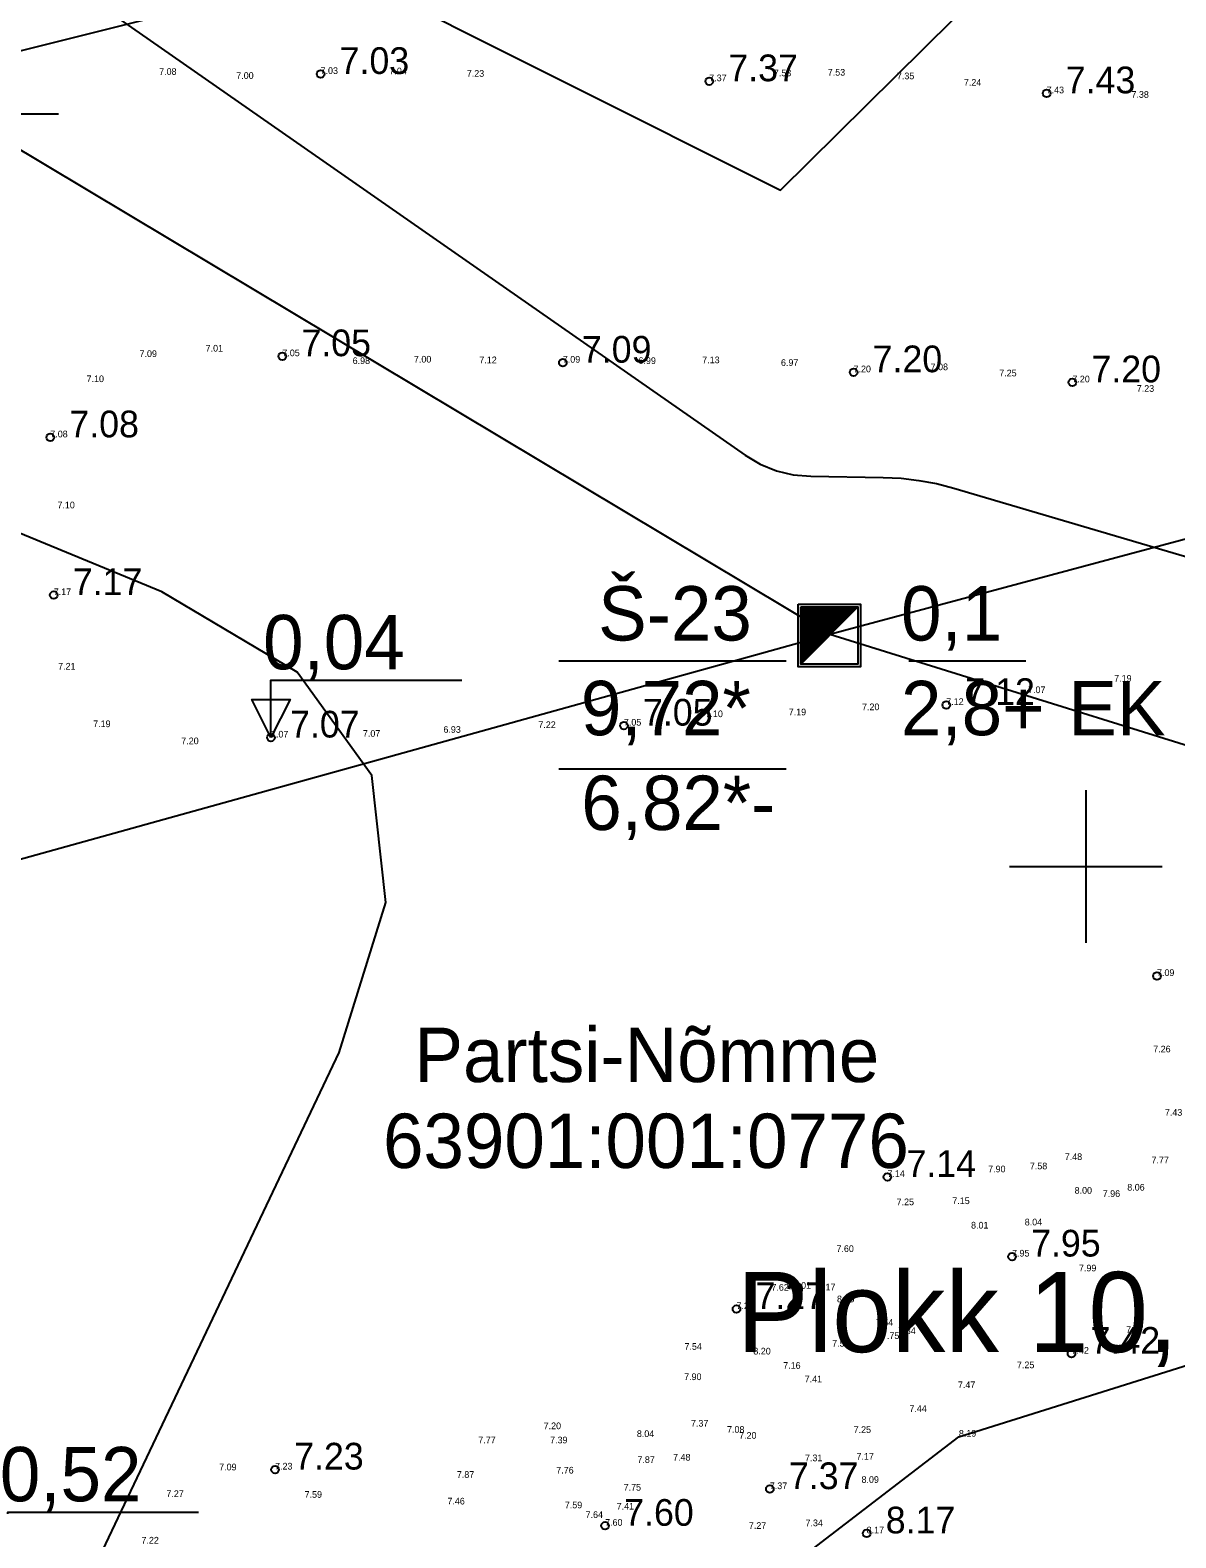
# Model space of a CAD drawing. Extents: x 433497 to 434382, y 6534486 to 6534993.
# Drawn here: x 433944.7 to 434004.7, y 6534764.8 to 6534843.8 of the extents above; entities that cross this region are included whole.
import ezdxf

# ---------------------------------------------------------------- set-up
doc = ezdxf.new("R2010")
doc.units = 0
for name, color, linetype in [('GEOLPUNKT', 7, 'Continuous'), ('jääkpaksus', 7, 'Continuous'), ('kataster', 7, 'Continuous'), ('KORGUS-EH2000', 7, 'Continuous'), ('l__x00e4__bil__x00f5__iked', 7, 'Continuous'), ('Lamami horisontaal', 7, 'Continuous'), ('MOOTKORG-EH2000', 7, 'Continuous'), ('PIIR', 7, 'Continuous'), ('VEEKOGU', 7, 'Continuous'), ('VORK', 7, 'Continuous')]:
    doc.layers.add(name, color=color, linetype=linetype)

msp = doc.modelspace()

# ---------------------------------------------------------------- linework, layer by layer
at = {"layer": 'GEOLPUNKT'}
for p, q in [((433985.055, 6534810.608), (433988.055, 6534813.608)), ((433985.055, 6534810.638), (433988.024, 6534813.608)), ((433985.055, 6534810.709), (433987.953, 6534813.608)), ((433985.055, 6534810.78), (433987.883, 6534813.608)), ((433985.055, 6534810.85), (433987.812, 6534813.608)), ((433985.055, 6534810.921), (433987.741, 6534813.608)), ((433985.055, 6534810.992), (433987.671, 6534813.608)), ((433985.055, 6534811.062), (433987.6, 6534813.608)), ((433985.055, 6534811.133), (433987.529, 6534813.608)), ((433985.055, 6534811.204), (433987.458, 6534813.608)), ((433985.055, 6534811.275), (433987.388, 6534813.608)), ((433985.055, 6534811.345), (433987.317, 6534813.608)), ((433985.055, 6534811.416), (433987.246, 6534813.608)), ((433985.055, 6534811.487), (433987.176, 6534813.608)), ((433985.055, 6534811.557), (433987.105, 6534813.608)), ((433985.055, 6534811.628), (433987.034, 6534813.608)), ((433985.055, 6534811.699), (433986.963, 6534813.608)), ((433985.055, 6534811.77), (433986.893, 6534813.608)), ((433985.055, 6534811.84), (433986.822, 6534813.608)), ((433985.055, 6534811.911), (433986.751, 6534813.608)), ((433985.055, 6534811.982), (433986.681, 6534813.608)), ((433985.055, 6534812.052), (433986.61, 6534813.608)), ((433985.055, 6534812.123), (433986.539, 6534813.608)), ((433985.055, 6534812.194), (433986.468, 6534813.608)), ((433985.055, 6534812.265), (433986.398, 6534813.608)), ((433985.055, 6534812.335), (433986.327, 6534813.608)), ((433985.055, 6534812.406), (433986.256, 6534813.608)), ((433985.055, 6534812.477), (433986.186, 6534813.608)), ((433985.055, 6534812.547), (433986.115, 6534813.608)), ((433985.055, 6534812.618), (433986.044, 6534813.608)), ((433985.055, 6534812.689), (433985.973, 6534813.608)), ((433985.055, 6534812.759), (433985.903, 6534813.608)), ((433985.055, 6534812.83), (433985.832, 6534813.608)), ((433985.055, 6534812.901), (433985.761, 6534813.608)), ((433985.055, 6534812.972), (433985.691, 6534813.608)), ((433985.055, 6534813.042), (433985.62, 6534813.608)), ((433985.055, 6534813.113), (433985.549, 6534813.608)), ((433985.055, 6534813.184), (433985.478, 6534813.608)), ((433985.055, 6534813.254), (433985.408, 6534813.608)), ((433985.055, 6534813.325), (433985.337, 6534813.608)), ((433985.055, 6534813.396), (433985.266, 6534813.608)), ((433985.055, 6534813.467), (433985.196, 6534813.608)), ((433985.055, 6534813.537), (433985.125, 6534813.608)), ((433986.555, 6534812.108), (433986.555, 6534812.108))]:
    msp.add_line(p, q, dxfattribs=at)
for points in [[(433984.914, 6534813.749), (433988.196, 6534813.749), (433988.196, 6534810.467), (433984.914, 6534810.467)], [(433985.055, 6534813.608), (433988.055, 6534813.608), (433988.055, 6534810.608), (433985.055, 6534810.608)]]:
    msp.add_lwpolyline(points, close=True, dxfattribs=at)
for points in [[(433972.379, 6534810.783), (433984.296, 6534810.783)], [(433990.718, 6534810.783), (433996.846, 6534810.783)], [(433972.379, 6534805.129), (433984.296, 6534805.129)]]:
    msp.add_lwpolyline(points, dxfattribs=at)
at = {"layer": 'jääkpaksus'}
for points in [[(433936.167, 6534836.451), (433936.167, 6534839.451), (433946.167, 6534839.451)], [(433957.299, 6534806.762), (433957.299, 6534809.762), (433967.299, 6534809.762)], [(433943.508, 6534763.157), (433943.508, 6534766.157), (433953.508, 6534766.157)]]:
    msp.add_lwpolyline(points, dxfattribs=at)
msp.add_lwpolyline([(433957.299, 6534806.762), (433956.299, 6534808.762), (433958.299, 6534808.762)], close=True, dxfattribs=at)
at = {"layer": 'KORGUS-EH2000'}
for centre in [(433959.898, 6534841.538), (433980.263, 6534841.158), (433997.941, 6534840.525), (433957.896, 6534826.746), (433972.591, 6534826.408), (433987.824, 6534825.906), (433999.289, 6534825.376), (433945.737, 6534822.494), (433945.916, 6534814.224), (433992.68, 6534808.467), (433975.791, 6534807.386), (433957.299, 6534806.762), (434003.722, 6534794.265), (433989.601, 6534783.734), (433996.128, 6534779.561), (433981.69, 6534776.808), (433999.243, 6534774.468), (433957.514, 6534768.398), (433983.437, 6534767.371), (433974.806, 6534765.45), (433988.511, 6534765.051)]:
    msp.add_circle(centre, 0.2, dxfattribs=at)
at = {"layer": 'l__x00e4__bil__x00f5__iked'}
for points in [[(433837.129, 6534901.88), (433863.279, 6534885.992), (433986.579, 6534812.177), (434090.185, 6534779.904), (434120.969, 6534768.153)], [(433620.07, 6534691.039), (433627.105, 6534692.187), (433736.834, 6534712.709), (433742.792, 6534710.723), (433822.234, 6534766.498), (433986.579, 6534812.177), (434120.472, 6534848.091), (434132.163, 6534850.175)]]:
    msp.add_lwpolyline(points, dxfattribs=at)
at = {"layer": 'Lamami horisontaal'}
for points in [[(433873.126, 6534888.995), (433873.76, 6534889.15), (433880.129, 6534889.137), (433886.285, 6534887.502), (433892.228, 6534884.245), (433982.141, 6534821.565), (433982.939, 6534821.09), (433983.78, 6534820.746), (433984.663, 6534820.534), (433985.588, 6534820.453), (433989.375, 6534820.395), (433990.317, 6534820.349), (433991.249, 6534820.24), (433992.172, 6534820.067), (433993.085, 6534819.831), (434065.946, 6534798.347)], [(433937.053, 6534740.112), (433960.879, 6534790.248), (433963.322, 6534798.12), (433962.586, 6534804.768), (433958.672, 6534810.191), (433951.578, 6534814.39), (433862.504, 6534851.176), (433857.642, 6534852.614), (433852.859, 6534852.881), (433848.155, 6534851.977), (433843.529, 6534849.902), (433823.019, 6534838.004), (433819.889, 6534836.728), (433817.507, 6534836.964), (433815.874, 6534838.714), (433814.99, 6534841.977), (433812.452, 6534861.972), (433812.459, 6534863.884), (433813.004, 6534865.497), (433813.579, 6534866.195)]]:
    msp.add_lwpolyline(points, dxfattribs=at)
at = {"layer": 'PIIR'}
msp.add_lwpolyline([(433924.608, 6534718.343), (433917.99, 6534737.895), (433917.54, 6534763.005), (433913.58, 6534784.995), (433921.17, 6534796.005), (433926.99, 6534825.75), (433941, 6534841.965), (433961.01, 6534846.975), (433983.99, 6534835.44), (434035.235, 6534886.132)], dxfattribs=at)
at = {"layer": 'VEEKOGU'}
msp.add_lwpolyline([(433990.248, 6534745.091), (433989.229, 6534747.928), (433987.385, 6534749.949), (433991.313, 6534753.223), (433990.848, 6534757.342), (433983.632, 6534758.762), (433984.921, 6534763.647), (433993.342, 6534770.119), (434007.795, 6534774.659), (434015.787, 6534777.524), (434021.334, 6534780.065), (434019.838, 6534775.271), (434024.742, 6534771.609), (434032.769, 6534771.363), (434040.593, 6534769.95), (434030.645, 6534764.016), (434026.863, 6534763.673), (434020.295, 6534765.501), (434016.352, 6534765.657), (434007.919, 6534762.574), (434004.918, 6534761.482), (434000.685, 6534758.332), (433996.369, 6534756.857), (433990.248, 6534745.091)], dxfattribs=at)
msp.add_lwpolyline([(433990.248, 6534745.091), (433989.229, 6534747.928), (433987.385, 6534749.949), (433991.313, 6534753.223), (433990.848, 6534757.342), (433983.632, 6534758.762), (433984.921, 6534763.647), (433993.342, 6534770.119), (434007.795, 6534774.659), (434015.787, 6534777.524), (434021.334, 6534780.065), (434019.838, 6534775.271), (434024.742, 6534771.609), (434032.769, 6534771.363), (434040.593, 6534769.95), (434030.645, 6534764.016), (434026.863, 6534763.673), (434020.295, 6534765.501), (434016.352, 6534765.657), (434007.919, 6534762.574), (434004.918, 6534761.482), (434000.685, 6534758.332), (433996.369, 6534756.857), (433990.248, 6534745.091)], dxfattribs=at)
at = {"layer": 'VORK'}
for p, q in [((434000, 6534804), (434000, 6534796)), ((433996, 6534800), (434004, 6534800))]:
    msp.add_line(p, q, dxfattribs=at)

# ---------------------------------------------------------------- texts
at = {"layer": 'GEOLPUNKT'}
for s, p in [('Š-23', (433974.442, 6534811.846)), ('0,1', (433990.31, 6534811.846)), ('9,72*', (433973.539, 6534806.881)), ('9,72*', (433973.539, 6534806.881)), ('2,8+', (433990.31, 6534806.881)), ('EK', (433999.082, 6534806.881)), ('6,82*-', (433973.558, 6534801.916))]:
    msp.add_text(s, height=2.85, dxfattribs=at).set_placement(p)
at = {"layer": 'jääkpaksus'}
for s, p in [('0,04', (433956.887, 6534810.337)), ('0,52', (433943.096, 6534766.732))]:
    msp.add_text(s, height=2.85, rotation=360, dxfattribs=at).set_placement(p)
at = {"layer": 'kataster'}
for s, p in [('Partsi-Nõmme', (433964.819, 6534788.705)), ('63901:001:0776', (433963.17, 6534784.202))]:
    msp.add_text(s, height=2.85, dxfattribs=at).set_placement(p)
at = {"layer": 'KORGUS-EH2000'}
for s, p in [('7.03', (433960.898, 6534841.538)), ('7.37', (433981.263, 6534841.158)), ('7.43', (433998.941, 6534840.525)), ('7.05', (433958.896, 6534826.746)), ('7.09', (433973.591, 6534826.408)), ('7.20', (433988.824, 6534825.906)), ('7.20', (434000.289, 6534825.376)), ('7.08', (433946.737, 6534822.494)), ('7.17', (433946.916, 6534814.224)), ('7.12', (433993.68, 6534808.467)), ('7.07', (433958.299, 6534806.762)), ('7.05', (433976.791, 6534807.386)), ('7.14', (433990.601, 6534783.734)), ('7.95', (433997.128, 6534779.561)), ('7.27', (433982.69, 6534776.808)), ('7.42', (434000.243, 6534774.468)), ('7.23', (433958.514, 6534768.398)), ('7.37', (433984.437, 6534767.371)), ('7.60', (433975.806, 6534765.45)), ('8.17', (433989.511, 6534765.051))]:
    msp.add_text(s, height=1.4, dxfattribs=at).set_placement(p)
at = {"layer": 'MOOTKORG-EH2000'}
for s, p in [('7.08', (433951.441, 6534841.489)), ('7.00', (433955.481, 6534841.279)), ('7.03', (433959.898, 6534841.538)), ('7.04', (433963.503, 6534841.52)), ('7.23', (433967.56, 6534841.392)), ('7.37', (433980.263, 6534841.158)), ('7.53', (433983.649, 6534841.42)), ('7.53', (433986.473, 6534841.453)), ('7.35', (433990.095, 6534841.261)), ('7.24', (433993.605, 6534840.921)), ('7.43', (433997.941, 6534840.525)), ('7.38', (434002.385, 6534840.288)), ('7.09', (433950.413, 6534826.705)), ('7.01', (433953.876, 6534826.99)), ('7.05', (433957.896, 6534826.746)), ('6.98', (433961.58, 6534826.335)), ('7.00', (433964.79, 6534826.414)), ('7.12', (433968.218, 6534826.378)), ('7.09', (433972.591, 6534826.408)), ('6.99', (433976.556, 6534826.34)), ('7.13', (433979.895, 6534826.379)), ('6.97', (433984.02, 6534826.239)), ('7.20', (433987.824, 6534825.906)), ('7.08', (433991.862, 6534826.014)), ('7.10', (433947.639, 6534825.388)), ('7.25', (433995.457, 6534825.689)), ('7.20', (433999.289, 6534825.376)), ('7.23', (434002.662, 6534824.88)), ('7.08', (433945.737, 6534822.494)), ('7.10', (433946.112, 6534818.773)), ('7.17', (433945.916, 6534814.224)), ('7.21', (433946.148, 6534810.323)), ('7.19', (434001.478, 6534809.691)), ('7.07', (433996.967, 6534809.088)), ('7.10', (433980.067, 6534807.83)), ('7.19', (433984.427, 6534807.926)), ('7.20', (433988.267, 6534808.194)), ('7.12', (433992.68, 6534808.467)), ('7.19', (433947.984, 6534807.306)), ('6.93', (433966.334, 6534807.009)), ('7.22', (433971.31, 6534807.26)), ('7.05', (433975.791, 6534807.386)), ('7.20', (433952.6, 6534806.411)), ('7.07', (433957.299, 6534806.762)), ('7.07', (433962.116, 6534806.8)), ('7.09', (434003.722, 6534794.265)), ('7.26', (434003.525, 6534790.26)), ('7.43', (434004.137, 6534786.94)), ('7.58', (433997.061, 6534784.131)), ('7.48', (433998.89, 6534784.619)), ('7.77', (434003.434, 6534784.441)), ('7.14', (433989.601, 6534783.734)), ('7.90', (433994.876, 6534783.978)), ('8.00', (433999.406, 6534782.854)), ('7.96', (434000.879, 6534782.685)), ('8.06', (434002.165, 6534783.017)), ('7.25', (433990.081, 6534782.251)), ('7.15', (433992.998, 6534782.31)), ('8.01', (433993.98, 6534781.028)), ('8.04', (433996.794, 6534781.192)), ('7.60', (433986.929, 6534779.799)), ('7.95', (433996.128, 6534779.561)), ('7.99', (433999.634, 6534778.782)), ('7.62', (433983.52, 6534777.773)), ('8.01', (433984.685, 6534777.871)), ('8.17', (433985.965, 6534777.786)), ('8.15', (433986.954, 6534777.164)), ('7.27', (433981.69, 6534776.808)), ('7.54', (433988.991, 6534775.935)), ('7.84', (433990.17, 6534775.496)), ('7.57', (434002.102, 6534775.55)), ('7.54', (433978.965, 6534774.673)), ('7.51', (433986.703, 6534774.839)), ('7.75', (433989.312, 6534775.243)), ('8.20', (433982.573, 6534774.428)), ('7.42', (433999.243, 6534774.468)), ('7.90', (433978.947, 6534773.085)), ('7.16', (433984.138, 6534773.676)), ('7.25', (433996.385, 6534773.708)), ('7.41', (433985.263, 6534772.967)), ('7.47', (433993.292, 6534772.663)), ('7.44', (433990.75, 6534771.42)), ('7.37', (433979.306, 6534770.648)), ('7.20', (433971.587, 6534770.513)), ('8.04', (433976.47, 6534770.102)), ('7.08', (433981.195, 6534770.322)), ('7.20', (433981.826, 6534770.008)), ('7.25', (433987.83, 6534770.316)), ('8.19', (433993.342, 6534770.119)), ('7.77', (433968.163, 6534769.772)), ('7.39', (433971.924, 6534769.771)), ('7.09', (433954.585, 6534768.353)), ('7.23', (433957.514, 6534768.398)), ('7.87', (433976.499, 6534768.742)), ('7.48', (433978.368, 6534768.866)), ('7.31', (433985.279, 6534768.834)), ('7.17', (433987.978, 6534768.911)), ('7.87', (433967.039, 6534767.963)), ('7.76', (433972.248, 6534768.189)), ('8.09', (433988.241, 6534767.698)), ('7.27', (433951.82, 6534766.958)), ('7.59', (433959.062, 6534766.917)), ('7.75', (433975.778, 6534767.292)), ('7.37', (433983.437, 6534767.371)), ('7.46', (433966.543, 6534766.567)), ('7.59', (433972.696, 6534766.367)), ('7.64', (433973.783, 6534765.859)), ('7.41', (433975.413, 6534766.301)), ('7.60', (433974.806, 6534765.45)), ('7.27', (433982.339, 6534765.289)), ('7.34', (433985.307, 6534765.428)), ('7.22', (433950.514, 6534764.518)), ('8.17', (433988.511, 6534765.051))]:
    msp.add_text(s, height=0.35, dxfattribs=at).set_placement(p)
at = {"layer": 'PIIR'}
msp.add_text('Plokk 10,13,14 Ta', height=4.2, dxfattribs=at).set_placement((433981.711, 6534774.553))

doc.saveas('drawing.dxf')
